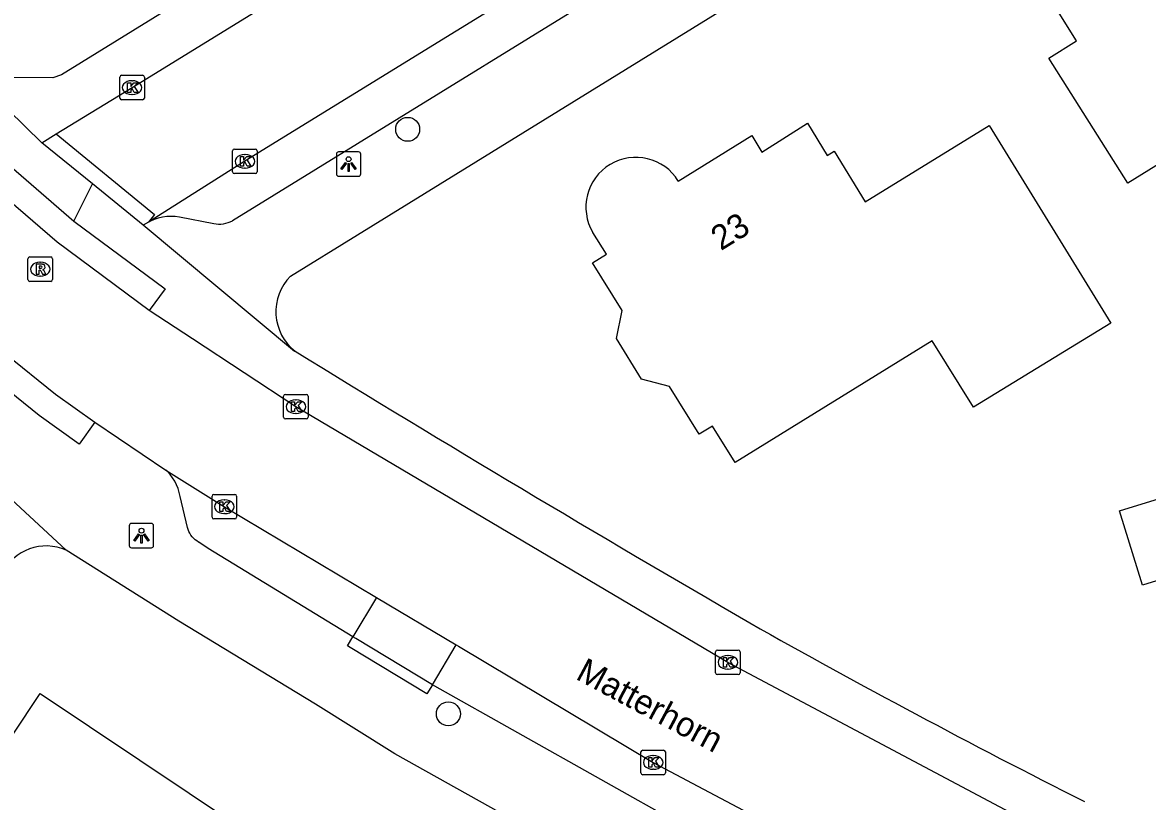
# Model space of a CAD drawing. Extents: x 158838 to 160074, y 386376 to 387776.
# Drawn here: x 159318.83 to 159364.72, y 386628.08 to 386659.86 of the extents above; entities that cross this region are included whole.
import ezdxf

# ---------------------------------------------------------------- set-up
doc = ezdxf.new("R2010")
doc.units = 0
for name, color, linetype in [('IMGEO_Boom', 7, 'Continuous'), ('IMGEO_Kolk', 7, 'Continuous'), ('IMGEO_Lichtpunt', 7, 'Continuous'), ('IMGEO_Openbare_ruimte_label', 7, 'Continuous'), ('IMGEO_Pand', 7, 'Continuous'), ('IMGEO_Pand_nummerreeks', 7, 'Continuous'), ('IMGEO_Rijbaan_lokaal_gesloten', 7, 'Continuous'), ('IMGEO_Rijbaan_lokaal_open', 7, 'Continuous'), ('IMGEO_Rioolput', 7, 'Continuous'), ('IMGEO_Voetpad_open', 7, 'Continuous')]:
    doc.layers.add(name, color=color, linetype=linetype)

msp = doc.modelspace()

# ---------------------------------------------------------------- linework, layer by layer
at = {"layer": 'IMGEO_Boom'}
for centre in [(159334.541, 386655.501), (159336.201, 386631.65)]:
    msp.add_circle(centre, 0.489, dxfattribs=at)
at = {"layer": 'IMGEO_Kolk'}
for p, q in [((159322.798, 386656.778), (159322.798, 386657.63)), ((159322.873, 386657.704), (159323.725, 386657.704)), ((159323.799, 386657.63), (159323.799, 386656.778)), ((159323.286, 386657.484), (159323.311, 386657.484)), ((159323.725, 386656.704), (159322.873, 386656.704)), ((159323.309, 386656.924), (159323.284, 386656.924)), ((159327.4, 386653.768), (159327.4, 386654.62)), ((159327.475, 386654.694), (159328.327, 386654.694)), ((159327.888, 386654.474), (159327.913, 386654.474)), ((159328.401, 386654.62), (159328.401, 386653.768)), ((159327.911, 386653.914), (159327.886, 386653.914)), ((159328.327, 386653.694), (159327.475, 386653.694)), ((159329.481, 386643.759), (159329.481, 386644.611)), ((159329.556, 386644.685), (159330.408, 386644.685)), ((159329.969, 386644.465), (159329.994, 386644.465)), ((159330.482, 386644.611), (159330.482, 386643.759)), ((159329.992, 386643.905), (159329.967, 386643.905)), ((159330.408, 386643.685), (159329.556, 386643.685)), ((159326.638, 386640.603), (159327.49, 386640.603)), ((159326.563, 386639.677), (159326.563, 386640.529)), ((159327.051, 386640.383), (159327.076, 386640.383)), ((159327.564, 386640.529), (159327.564, 386639.677)), ((159327.074, 386639.823), (159327.049, 386639.823)), ((159327.49, 386639.603), (159326.638, 386639.603)), ((159347.101, 386633.327), (159347.101, 386634.179)), ((159347.176, 386634.253), (159348.028, 386634.253)), ((159348.102, 386634.179), (159348.102, 386633.327)), ((159347.589, 386634.033), (159347.614, 386634.033)), ((159348.028, 386633.253), (159347.176, 386633.253)), ((159347.612, 386633.473), (159347.587, 386633.473)), ((159344.055, 386629.244), (159344.055, 386630.096)), ((159344.13, 386630.17), (159344.982, 386630.17)), ((159345.056, 386630.096), (159345.056, 386629.244)), ((159344.543, 386629.95), (159344.568, 386629.95)), ((159344.982, 386629.17), (159344.13, 386629.17)), ((159344.566, 386629.39), (159344.541, 386629.39))]:
    msp.add_line(p, q, dxfattribs=at)
for points in [[(159322.798, 386656.778), (159322.798, 386657.63)], [(159322.873, 386657.704), (159323.725, 386657.704)], [(159323.799, 386657.63), (159323.799, 386656.778)], [(159323.119, 386657.404), (159323.242, 386657.404), (159323.242, 386657.253), (159323.372, 386657.404), (159323.536, 386657.404), (159323.39, 386657.253), (159323.543, 386657.004), (159323.391, 386657.004), (159323.306, 386657.168), (159323.242, 386657.101), (159323.242, 386657.004), (159323.119, 386657.004), (159323.119, 386657.404)], [(159323.725, 386656.704), (159322.873, 386656.704)], [(159327.4, 386653.768), (159327.4, 386654.62)], [(159327.475, 386654.694), (159328.327, 386654.694)], [(159327.721, 386654.394), (159327.844, 386654.394), (159327.844, 386654.243), (159327.974, 386654.394), (159328.138, 386654.394), (159327.992, 386654.243), (159328.145, 386653.994), (159327.993, 386653.994), (159327.908, 386654.158), (159327.844, 386654.091), (159327.844, 386653.994), (159327.721, 386653.994), (159327.721, 386654.394)], [(159328.401, 386654.62), (159328.401, 386653.768)], [(159328.327, 386653.694), (159327.475, 386653.694)], [(159329.481, 386643.759), (159329.481, 386644.611)], [(159329.556, 386644.685), (159330.408, 386644.685)], [(159329.802, 386644.385), (159329.925, 386644.385), (159329.925, 386644.234), (159330.055, 386644.385), (159330.219, 386644.385), (159330.073, 386644.234), (159330.226, 386643.985), (159330.074, 386643.985), (159329.989, 386644.149), (159329.925, 386644.082), (159329.925, 386643.985), (159329.802, 386643.985), (159329.802, 386644.385)], [(159330.482, 386644.611), (159330.482, 386643.759)], [(159330.408, 386643.685), (159329.556, 386643.685)], [(159326.638, 386640.603), (159327.49, 386640.603)], [(159326.563, 386639.677), (159326.563, 386640.529)], [(159326.884, 386640.303), (159327.007, 386640.303), (159327.007, 386640.152), (159327.137, 386640.303), (159327.301, 386640.303), (159327.155, 386640.152), (159327.308, 386639.903), (159327.156, 386639.903), (159327.071, 386640.067), (159327.007, 386640), (159327.007, 386639.903), (159326.884, 386639.903), (159326.884, 386640.303)], [(159327.564, 386640.529), (159327.564, 386639.677)], [(159327.49, 386639.603), (159326.638, 386639.603)], [(159347.101, 386633.327), (159347.101, 386634.179)], [(159347.176, 386634.253), (159348.028, 386634.253)], [(159348.102, 386634.179), (159348.102, 386633.327)], [(159347.422, 386633.953), (159347.545, 386633.953), (159347.545, 386633.802), (159347.675, 386633.953), (159347.839, 386633.953), (159347.693, 386633.802), (159347.846, 386633.553), (159347.694, 386633.553), (159347.609, 386633.717), (159347.545, 386633.65), (159347.545, 386633.553), (159347.422, 386633.553), (159347.422, 386633.953)], [(159348.028, 386633.253), (159347.176, 386633.253)], [(159344.055, 386629.244), (159344.055, 386630.096)], [(159344.13, 386630.17), (159344.982, 386630.17)], [(159345.056, 386630.096), (159345.056, 386629.244)], [(159344.376, 386629.87), (159344.499, 386629.87), (159344.499, 386629.719), (159344.629, 386629.87), (159344.793, 386629.87), (159344.647, 386629.719), (159344.8, 386629.47), (159344.648, 386629.47), (159344.563, 386629.634), (159344.499, 386629.567), (159344.499, 386629.47), (159344.376, 386629.47), (159344.376, 386629.87)], [(159344.982, 386629.17), (159344.13, 386629.17)]]:
    msp.add_lwpolyline(points, dxfattribs=at)
for centre, start, end in [((159322.875, 386657.628), 91.552, 178.448), ((159322.875, 386657.628), 91.552, 178.448), ((159323.723, 386657.628), 1.552, 88.448), ((159323.723, 386657.628), 1.552, 88.448), ((159322.875, 386656.78), 181.552, 268.448), ((159322.875, 386656.78), 181.552, 268.448), ((159323.723, 386656.78), 271.552, 358.448), ((159323.723, 386656.78), 271.552, 358.448), ((159327.477, 386654.618), 91.552, 178.448), ((159327.477, 386654.618), 91.552, 178.448), ((159328.325, 386654.618), 1.552, 88.448), ((159328.325, 386654.618), 1.552, 88.448), ((159327.477, 386653.77), 181.552, 268.448), ((159327.477, 386653.77), 181.552, 268.448), ((159328.325, 386653.77), 271.552, 358.448), ((159328.325, 386653.77), 271.552, 358.448), ((159329.558, 386644.609), 91.552, 178.448), ((159329.558, 386644.609), 91.552, 178.448), ((159330.406, 386644.609), 1.552, 88.448), ((159330.406, 386644.609), 1.552, 88.448), ((159329.558, 386643.761), 181.552, 268.448), ((159329.558, 386643.761), 181.552, 268.448), ((159330.406, 386643.761), 271.552, 358.448), ((159330.406, 386643.761), 271.552, 358.448), ((159326.64, 386640.527), 91.552, 178.448), ((159326.64, 386640.527), 91.552, 178.448), ((159327.488, 386640.527), 1.552, 88.448), ((159327.488, 386640.527), 1.552, 88.448), ((159326.64, 386639.679), 181.552, 268.448), ((159326.64, 386639.679), 181.552, 268.448), ((159327.488, 386639.679), 271.552, 358.448), ((159327.488, 386639.679), 271.552, 358.448), ((159347.178, 386634.177), 91.552, 178.448), ((159347.178, 386634.177), 91.552, 178.448), ((159348.026, 386634.177), 1.552, 88.448), ((159348.026, 386634.177), 1.552, 88.448), ((159347.178, 386633.329), 181.552, 268.448), ((159347.178, 386633.329), 181.552, 268.448), ((159348.026, 386633.329), 271.552, 358.448), ((159348.026, 386633.329), 271.552, 358.448), ((159344.132, 386630.094), 91.552, 178.448), ((159344.132, 386630.094), 91.552, 178.448), ((159344.98, 386630.094), 1.552, 88.448), ((159344.98, 386630.094), 1.552, 88.448), ((159344.132, 386629.246), 181.552, 268.448), ((159344.132, 386629.246), 181.552, 268.448), ((159344.98, 386629.246), 271.552, 358.448), ((159344.98, 386629.246), 271.552, 358.448)]:
    msp.add_arc(centre, 0.0765, start, end, dxfattribs=at)
for centre, major_axis, ratio, start_param, end_param in [((159323.285, 386657.204), (-0.387, 0.002), 0.722429, 4.712389, 7.853982), ((159323.31, 386657.204), (-0.39, 0.002), 0.717154, 1.570796, 4.712389), ((159327.887, 386654.194), (-0.387, 0.002), 0.722429, 4.712389, 7.853982), ((159327.912, 386654.194), (-0.39, 0.002), 0.717154, 1.570796, 4.712389), ((159329.968, 386644.185), (-0.387, 0.002), 0.722429, 4.712389, 7.853982), ((159329.993, 386644.185), (-0.39, 0.002), 0.717154, 1.570796, 4.712389), ((159327.05, 386640.103), (-0.387, 0.002), 0.722429, 4.712389, 7.853982), ((159327.075, 386640.103), (-0.39, 0.002), 0.717154, 1.570796, 4.712389), ((159347.588, 386633.753), (-0.387, 0.002), 0.722429, 4.712389, 7.853982), ((159347.613, 386633.753), (-0.39, 0.002), 0.717154, 1.570796, 4.712389), ((159344.542, 386629.67), (-0.387, 0.002), 0.722429, 4.712389, 7.853982), ((159344.567, 386629.67), (-0.39, 0.002), 0.717154, 1.570796, 4.712389)]:
    msp.add_ellipse(centre, major_axis=major_axis, ratio=ratio, start_param=start_param, end_param=end_param, dxfattribs=at)
at = {"layer": 'IMGEO_Lichtpunt'}
for p, q in [((159331.632, 386654.486), (159331.632, 386653.679)), ((159331.632, 386654.486), (159331.632, 386653.679)), ((159332.534, 386654.581), (159331.726, 386654.581)), ((159332.534, 386654.581), (159331.726, 386654.581)), ((159332.628, 386653.679), (159332.628, 386654.486)), ((159332.628, 386653.679), (159332.628, 386654.486)), ((159331.726, 386653.585), (159332.534, 386653.585)), ((159331.726, 386653.585), (159332.534, 386653.585)), ((159323.183, 386639.328), (159323.183, 386638.521)), ((159323.183, 386639.328), (159323.183, 386638.521)), ((159324.085, 386639.423), (159323.277, 386639.423)), ((159324.085, 386639.423), (159323.277, 386639.423)), ((159324.179, 386638.521), (159324.179, 386639.328)), ((159324.179, 386638.521), (159324.179, 386639.328)), ((159323.277, 386638.427), (159324.085, 386638.427)), ((159323.277, 386638.427), (159324.085, 386638.427))]:
    msp.add_line(p, q, dxfattribs=at)
for points in [[(159332.006, 386654.15), (159332.045, 386654.122), (159331.857, 386653.86), (159331.819, 386653.887), (159332.006, 386654.15)], [(159332.108, 386654.102), (159332.155, 386654.102), (159332.155, 386653.78), (159332.108, 386653.78), (159332.108, 386654.102)], [(159332.218, 386654.122), (159332.256, 386654.149), (159332.443, 386653.887), (159332.404, 386653.859), (159332.218, 386654.122)], [(159323.557, 386638.992), (159323.596, 386638.964), (159323.408, 386638.702), (159323.37, 386638.729), (159323.557, 386638.992)], [(159323.659, 386638.944), (159323.706, 386638.944), (159323.706, 386638.622), (159323.659, 386638.622), (159323.659, 386638.944)], [(159323.769, 386638.964), (159323.807, 386638.991), (159323.994, 386638.729), (159323.955, 386638.701), (159323.769, 386638.964)]]:
    msp.add_lwpolyline(points, dxfattribs=at)
for centre in [(159332.131, 386654.284), (159323.682, 386639.126)]:
    msp.add_circle(centre, 0.0994, dxfattribs=at)
for centre, start, end in [((159331.726, 386654.486), 90, 180), ((159331.726, 386654.486), 90, 180), ((159332.534, 386654.486), 0, 90), ((159332.534, 386654.486), 0, 90), ((159331.726, 386653.679), 180, 270), ((159331.726, 386653.679), 180, 270), ((159332.534, 386653.679), 270, 0), ((159332.534, 386653.679), 270, 360), ((159323.277, 386639.328), 90, 180), ((159323.277, 386639.328), 90, 180), ((159324.085, 386639.328), 0, 90), ((159324.085, 386639.328), 0, 90), ((159323.277, 386638.521), 180, 270), ((159323.277, 386638.521), 180, 270), ((159324.085, 386638.521), 270, 0), ((159324.085, 386638.521), 270, 360)]:
    msp.add_arc(centre, 0.0946, start, end, dxfattribs=at)
at = {"layer": 'IMGEO_Pand'}
for points in [[(159376.911, 386661.27), (159378.44, 386658.766), (159373.204, 386655.525), (159371.628, 386658.071), (159363.923, 386653.301), (159360.694, 386658.406), (159361.818, 386659.117), (159359.894, 386662.215), (159360.878, 386662.842), (159360.573, 386663.403), (159362.537, 386664.626), (159362.878, 386664.069), (159366.526, 386666.314), (159367.564, 386664.639), (159368.463, 386663.189), (159370.25, 386664.295), (159370.813, 386663.357), (159374.263, 386665.511), (159376.911, 386661.27)], [(159345.58, 386653.392), (159348.575, 386655.247), (159348.982, 386654.575), (159350.85, 386655.754), (159351.649, 386654.432), (159351.936, 386654.613), (159353.209, 386652.542), (159358.258, 386655.653), (159363.228, 386647.598)], [(159363.228, 386647.598), (159357.622, 386644.159), (159355.94, 386646.866), (159347.895, 386641.903), (159346.976, 386643.392), (159346.425, 386643.061), (159345.219, 386645.009), (159344.081, 386645.309), (159343.058, 386646.97), (159343.289, 386648.113), (159342.084, 386650.056), (159342.645, 386650.404), (159342.093, 386651.29)], [(159363.581, 386639.937), (159367.153, 386641.043), (159368.094, 386638.004), (159364.521, 386636.898), (159363.581, 386639.937)], [(159317.252, 386629.043), (159319.546, 386632.48), (159331.703, 386624.349), (159326.892, 386617.237)]]:
    msp.add_lwpolyline(points, dxfattribs=at)
msp.add_arc((159343.847, 386652.323), 2.036, 31.6593, 210.5047, dxfattribs=at)
at = {"layer": 'IMGEO_Rijbaan_lokaal_gesloten'}
for points in [[(159323.991, 386648.114), (159320.24, 386650.892), (159314.969, 386655.443)], [(159314.004, 386649.679), (159320.182, 386644.697), (159321.779, 386643.55)], [(159367.111, 386623.537), (159361.292, 386626.474), (159347.601, 386633.751), (159329.982, 386644.184), (159325.765, 386646.95), (159323.991, 386648.114)], [(159321.779, 386643.55), (159324.681, 386641.593)], [(159324.681, 386641.593), (159327.065, 386640.104), (159333.267, 386636.405)], [(159333.267, 386636.405), (159336.517, 386634.466)], [(159336.517, 386634.466), (159336.613, 386634.409), (159344.556, 386629.671), (159350.044, 386626.76)]]:
    msp.add_lwpolyline(points, dxfattribs=at)
at = {"layer": 'IMGEO_Rijbaan_lokaal_open'}
for points in [[(159320.197, 386655.316), (159323.299, 386657.203), (159338.172, 386666.37), (159353.058, 386675.561), (159358.099, 386678.643)], [(159347.032, 386665.982), (159340.827, 386662.17), (159327.901, 386654.195), (159323.963, 386651.717)], [(159319.623, 386654.955), (159320.197, 386655.316)], [(159320.197, 386655.316), (159324.213, 386652.028), (159323.963, 386651.717)], [(159321.688, 386653.27), (159319.623, 386654.955)], [(159323.753, 386651.584), (159321.688, 386653.27)], [(159323.963, 386651.717), (159323.753, 386651.584)]]:
    msp.add_lwpolyline(points, dxfattribs=at)
at = {"layer": 'IMGEO_Rioolput'}
for p, q in [((159319.052, 386649.369), (159319.052, 386650.221)), ((159319.127, 386650.295), (159319.979, 386650.295)), ((159320.053, 386650.221), (159320.053, 386649.369)), ((159319.54, 386650.075), (159319.565, 386650.075)), ((159319.979, 386649.295), (159319.127, 386649.295)), ((159319.563, 386649.515), (159319.538, 386649.515))]:
    msp.add_line(p, q, dxfattribs=at)
for points in [[(159319.052, 386649.369), (159319.052, 386650.221)], [(159319.127, 386650.295), (159319.979, 386650.295)], [(159320.053, 386650.221), (159320.053, 386649.369)], [(159319.641, 386649.993), (159319.389, 386649.995), (159319.389, 386649.595)], [(159319.389, 386649.595), (159319.513, 386649.595), (159319.513, 386649.757), (159319.524, 386649.757)], [(159319.567, 386649.914), (159319.513, 386649.914), (159319.513, 386649.833)], [(159319.513, 386649.833), (159319.565, 386649.833)], [(159319.979, 386649.295), (159319.127, 386649.295)], [(159319.571, 386649.728), (159319.642, 386649.595), (159319.782, 386649.595), (159319.717, 386649.721)]]:
    msp.add_lwpolyline(points, dxfattribs=at)
for centre, radius, start, end in [((159319.129, 386650.219), 0.0765, 91.552, 178.448), ((159319.129, 386650.219), 0.0765, 91.552, 178.448), ((159319.977, 386650.219), 0.0765, 1.552, 88.448), ((159319.977, 386650.219), 0.0765, 1.552, 88.448), ((159319.523, 386649.704), 0.0533, 26.0293, 88.6989), ((159319.549, 386650.022), 0.19, 274.7715, 282.9687), ((159319.573, 386649.818), 0.0964, 77.0061, 93.1865), ((159319.587, 386649.875), 0.0378, 276.6634, 79.6772), ((159319.64, 386649.883), 0.109, 350.3612, 89.416), ((159319.638, 386649.883), 0.112, 277.5842, 350.9817), ((159319.622, 386649.668), 0.108, 29.5134, 73.7905), ((159319.129, 386649.371), 0.0765, 181.552, 268.448), ((159319.129, 386649.371), 0.0765, 181.552, 268.448), ((159319.977, 386649.371), 0.0765, 271.552, 358.448), ((159319.977, 386649.371), 0.0765, 271.552, 358.448)]:
    msp.add_arc(centre, radius, start, end, dxfattribs=at)
for centre, major_axis, ratio, start_param, end_param in [((159319.539, 386649.795), (-0.387, 0.002), 0.722429, 4.712389, 7.853982), ((159319.564, 386649.795), (-0.39, 0.002), 0.717154, 1.570796, 4.712389)]:
    msp.add_ellipse(centre, major_axis=major_axis, ratio=ratio, start_param=start_param, end_param=end_param, dxfattribs=at)
at = {"layer": 'IMGEO_Voetpad_open'}
for points in [[(159432.071, 386726.541), (159398.233, 386705.745), (159320.416, 386657.723), (159320.063, 386657.598), (159317.182, 386657.619), (159316.858, 386657.646)], [(159329.763, 386649.508), (159404.197, 386695.456), (159405.088, 386695.997), (159408.523, 386697.788), (159412.19, 386699.306), (159415.977, 386700.489)], [(159347.971, 386664.453), (159327.394, 386651.77), (159327.378, 386651.76), (159327.291, 386651.716), (159327.201, 386651.68), (159327.109, 386651.652), (159327.014, 386651.632), (159326.917, 386651.621), (159326.821, 386651.619), (159326.724, 386651.625), (159326.628, 386651.64), (159325.23, 386651.918), (159325.058, 386651.941), (159324.884, 386651.949), (159324.711, 386651.941), (159324.538, 386651.918), (159324.369, 386651.88), (159324.204, 386651.826), (159324.044, 386651.758), (159323.963, 386651.717)], [(159319.623, 386654.955), (159316.858, 386657.646)], [(159314.969, 386655.443), (159315.688, 386656.276), (159320.928, 386651.751)], [(159320.928, 386651.751), (159321.688, 386653.27)], [(159320.928, 386651.751), (159324.646, 386648.998), (159323.991, 386648.114)], [(159329.951, 386646.444), (159329.93, 386646.438), (159323.753, 386651.584)], [(159321.779, 386643.55), (159321.137, 386642.657), (159319.515, 386643.821), (159313.313, 386648.823), (159314.004, 386649.679)], [(159332.308, 386634.797), (159326.401, 386638.4), (159326.023, 386638.655), (159326.013, 386638.661), (159325.94, 386638.706), (159325.872, 386638.758), (159325.809, 386638.816), (159325.751, 386638.879), (159325.699, 386638.947), (159325.654, 386639.019), (159325.615, 386639.096), (159325.583, 386639.175), (159325.558, 386639.257), (159325.256, 386640.521), (159325.223, 386640.683), (159325.175, 386640.841), (159325.114, 386640.995), (159325.039, 386641.142), (159324.951, 386641.282), (159324.851, 386641.414), (159324.74, 386641.536), (159324.681, 386641.593)], [(159320.616, 386638.324), (159317.618, 386641.092)], [(159417.314, 386592.1), (159409.486, 386594.837), (159405.916, 386596.132), (159403.97, 386596.822), (159400.475, 386598.135), (159386.22, 386603.858), (159382.649, 386605.402), (159367.084, 386612.517), (159363.661, 386614.16), (159351.051, 386620.582), (159347.709, 386622.366), (159334.021, 386630.024), (159330.778, 386632.045), (159325.211, 386635.435), (159320.616, 386638.324)], [(159333.267, 386636.405), (159332.308, 386634.797)], [(159335.549, 386632.842), (159335.322, 386632.466), (159332.199, 386634.358), (159332.085, 386634.427), (159332.308, 386634.797)], [(159335.549, 386632.842), (159332.422, 386634.727), (159332.308, 386634.797)], [(159335.549, 386632.842), (159336.517, 386634.466)], [(159349.197, 386625.162), (159335.645, 386632.784), (159335.549, 386632.842)]]:
    msp.add_lwpolyline(points, dxfattribs=at)
for centre, radius, start, end in [((159331.21, 386648.059), 2.048, 134.9577, 232.0646), ((159790.309, 387395.826), 879.49, 238.436929, 239.84473), ((159319.795, 386636.513), 1.988, 65.6009, 154.6987), ((159511.952, 386925.067), 332.636, 240.56851, 243.23292)]:
    msp.add_arc(centre, radius, start, end, dxfattribs=at)

# ---------------------------------------------------------------- texts
at = {"layer": 'IMGEO_Openbare_ruimte_label'}
msp.add_text('Matterhorn', height=1, rotation=331.8467, dxfattribs=at).set_placement((159341.35, 386633.092))
at = {"layer": 'IMGEO_Pand_nummerreeks'}
msp.add_text('23', height=1, rotation=31.7727, dxfattribs=at).set_placement((159347.317, 386650.528))

doc.saveas('drawing.dxf')
